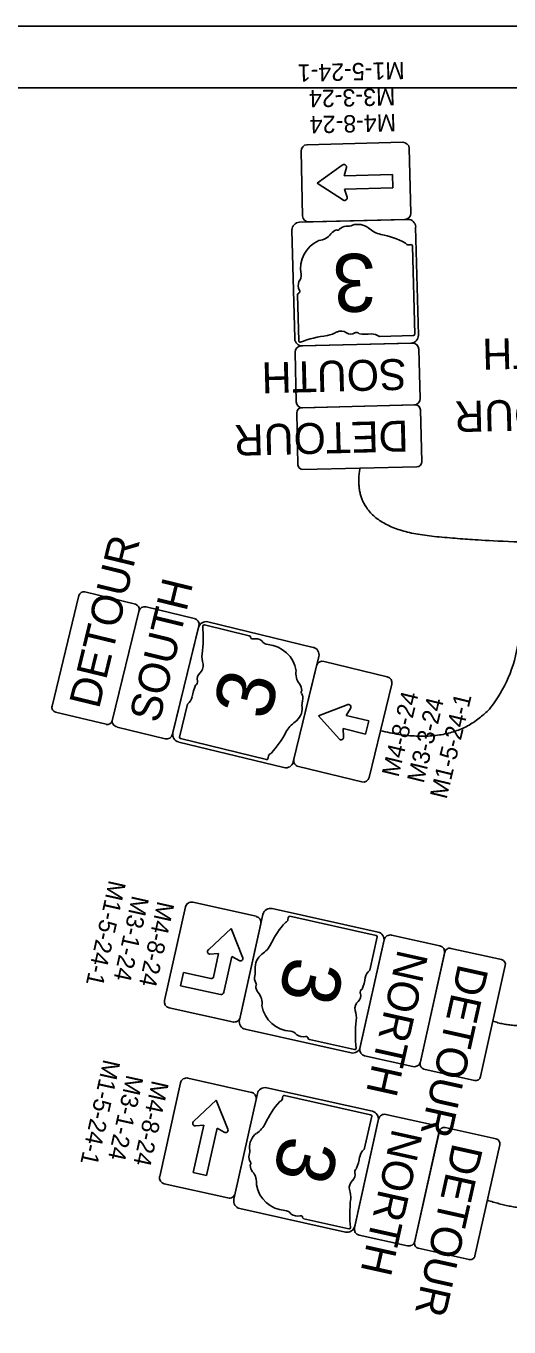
# Model space of a CAD drawing. Extents: x -15.3 to 34, y 0 to 22.
# Drawn here: x 16.96 to 20.86, y 11.48 to 22 of the extents above; entities that cross this region are included whole.
import ezdxf

# ---------------------------------------------------------------- set-up
doc = ezdxf.new("R2010")
doc.units = 0
for name, color, linetype in [('SC_Scratch1', 7, 'Continuous'), ('SH_Border', 7, 'Continuous'), ('SH_Cut_Line', 7, 'Continuous'), ('SH_Text', 7, 'Continuous'), ('SN_P_Signs', 7, 'Continuous')]:
    doc.layers.add(name, color=color, linetype=linetype)

msp = doc.modelspace()

# ---------------------------------------------------------------- linework, layer by layer
at = {"layer": 'SH_Border'}
msp.add_lwpolyline([(1.5, 21.5), (33.5, 21.5), (33.5, 0.5), (1.5, 0.5)], close=True, dxfattribs=at)
at = {"layer": 'SH_Cut_Line'}
msp.add_lwpolyline([(0, 0), (34, 0), (34, 22), (0, 22)], close=True, dxfattribs=at)
at = {"layer": 'SH_Text'}
for points in [[(19.655, 18.426), (19.572, 17.947), (20.883, 17.807), (23.028, 17.829), (24.003, 17.194), (24.244, 16.85)], [(19.821, 16.303), (20.813, 16.063), (21.093, 18.199), (23.713, 17.06), (23.897, 16.988), (23.961, 16.647)], [(20.729, 13.956), (21.193, 13.792), (22.671, 14.944), (23.628, 16.352), (23.835, 16.339)], [(20.684, 12.508), (21.281, 12.313), (22, 12.975), (23.853, 16.417), (24.116, 16.271)]]:
    msp.add_open_spline(points, degree=2, dxfattribs=at)
at = {"layer": 'SN_P_Signs'}
for p, q in [((19.227, 21.04), (20.002, 21.06)), ((19.192, 20.464), (19.179, 20.989)), ((20.053, 21.012), (20.067, 20.487)), ((19.511, 20.875), (19.31, 20.73)), ((19.528, 20.79), (19.546, 20.855)), ((19.31, 20.73), (19.521, 20.593)), ((19.918, 20.8), (19.528, 20.79)), ((19.921, 20.691), (19.918, 20.8)), ((19.531, 20.681), (19.921, 20.691)), ((19.552, 20.617), (19.531, 20.681)), ((20.018, 20.436), (19.244, 20.416)), ((20.097, 19.509), (20.079, 20.221)), ((19.151, 19.827), (19.161, 19.455)), ((19.151, 19.827), (19.151, 19.827)), ((19.814, 19.49), (20.088, 19.497)), ((19.141, 18.962), (19.131, 19.362)), ((19.18, 19.414), (20.079, 19.437)), ((20.131, 19.388), (20.141, 18.988)), ((20.092, 18.937), (19.193, 18.914)), ((17.656, 16.394), (17.868, 17.268)), ((17.929, 17.305), (18.317, 17.211)), ((18.354, 17.15), (18.142, 16.276)), ((18.761, 17.07), (18.4, 17.158)), ((18.761, 17.07), (18.761, 17.07)), ((19.122, 16.074), (19.305, 16.827)), ((19.365, 16.864), (19.875, 16.74)), ((19.912, 16.679), (19.729, 15.926)), ((18.262, 16.518), (18.197, 16.252)), ((19.32, 16.425), (19.551, 16.512)), ((19.487, 16.238), (19.32, 16.425)), ((19.58, 16.484), (19.545, 16.426)), ((19.545, 16.426), (19.727, 16.382)), ((18.081, 16.239), (17.693, 16.333)), ((19.701, 16.275), (19.519, 16.32)), ((19.519, 16.32), (19.523, 16.253)), ((19.727, 16.382), (19.701, 16.275)), ((18.207, 16.24), (18.899, 16.072)), ((19.669, 15.889), (19.159, 16.013)), ((18.077, 14.123), (18.245, 14.879)), ((18.305, 14.917), (18.817, 14.803)), ((18.855, 14.743), (18.687, 13.987)), ((19.785, 14.648), (19.09, 14.803)), ((18.614, 14.704), (18.434, 14.535)), ((18.706, 14.474), (18.614, 14.704)), ((19.735, 14.368), (19.795, 14.636)), ((19.91, 14.651), (20.301, 14.564)), ((19.655, 13.735), (19.851, 14.613)), ((18.44, 14.497), (18.513, 14.502)), ((18.513, 14.502), (18.471, 14.312)), ((18.555, 14.189), (18.62, 14.478)), ((18.62, 14.478), (18.684, 14.443)), ((20.339, 14.504), (20.143, 13.626)), ((18.231, 14.349), (18.207, 14.242)), ((18.231, 14.349), (18.207, 14.242)), ((18.452, 14.3), (18.231, 14.349)), ((18.207, 14.242), (18.528, 14.171)), ((18.555, 14.189), (18.555, 14.189)), ((18.627, 13.949), (18.115, 14.063)), ((19.247, 13.807), (19.61, 13.726)), ((19.247, 13.807), (19.247, 13.807)), ((20.083, 13.588), (19.693, 13.675)), ((18.778, 13.38), (18.266, 13.495)), ((18.206, 13.457), (18.038, 12.7)), ((18.314, 13.147), (18.495, 13.316)), ((18.495, 13.316), (18.589, 13.083)), ((18.648, 12.564), (18.816, 13.321)), ((19.74, 13.199), (19.045, 13.354)), ((19.61, 12.286), (19.806, 13.164)), ((19.69, 12.919), (19.75, 13.187)), ((19.865, 13.202), (20.256, 13.115)), ((18.309, 12.733), (18.394, 13.114)), ((18.394, 13.114), (18.327, 13.108)), ((18.501, 13.09), (18.416, 12.709)), ((18.559, 13.057), (18.501, 13.09)), ((20.294, 13.056), (20.098, 12.177)), ((18.416, 12.709), (18.309, 12.733)), ((18.075, 12.641), (18.588, 12.526)), ((18.648, 12.564), (18.648, 12.564)), ((19.202, 12.358), (19.565, 12.277)), ((19.202, 12.358), (19.202, 12.358)), ((20.038, 12.139), (19.648, 12.226))]:
    msp.add_line(p, q, dxfattribs=at)
for points in [[(20.041, 20.436), (19.166, 20.414)], [(19.106, 20.35), (19.128, 19.475)], [(20.128, 19.501), (20.105, 20.375)], [(19.192, 19.414), (20.067, 19.436)], [(20.102, 18.937), (19.183, 18.914)], [(19.144, 18.873), (19.154, 18.453)], [(20.154, 18.478), (20.143, 18.898)], [(19.195, 18.414), (20.115, 18.437)], [(17.385, 17.396), (17.168, 16.502)], [(17.841, 17.326), (17.433, 17.425)], [(17.654, 16.384), (17.871, 17.278)], [(19.277, 16.977), (18.427, 17.184)], [(18.351, 17.138), (18.145, 16.288)], [(19.116, 16.052), (19.323, 16.902)], [(17.197, 16.454), (17.605, 16.355)], [(18.191, 16.212), (19.041, 16.006)], [(19.801, 14.676), (18.947, 14.866)], [(18.872, 14.818), (18.682, 13.964)], [(19.658, 13.747), (19.848, 14.601)], [(20.341, 14.514), (20.141, 13.616)], [(20.799, 14.453), (20.389, 14.544)], [(20.629, 13.507), (20.829, 14.405)], [(18.729, 13.89), (19.583, 13.699)], [(20.171, 13.568), (20.581, 13.477)], [(18.827, 13.37), (18.637, 12.516)], [(19.756, 13.227), (18.902, 13.417)], [(19.613, 12.298), (19.803, 13.152)], [(20.296, 13.065), (20.096, 12.167)], [(20.754, 13.004), (20.344, 13.096)], [(20.584, 12.059), (20.784, 12.957)], [(18.684, 12.441), (19.538, 12.251)], [(20.126, 12.12), (20.536, 12.028)]]:
    msp.add_lwpolyline(points, dxfattribs=at)
for centre, radius, start, end in [((19.229, 20.99), 0.05, 91.4753, 181.4753), ((20.003, 21.01), 0.05, 1.4753, 91.4753), ((19.526, 20.86), 0.0209, 344.2707, 136.4849), ((19.532, 20.611), 0.0209, 236.8865, 18.6799), ((19.168, 20.351), 0.0625, 91.4753, 181.4753), ((19.242, 20.466), 0.05, 181.4753, 271.4753), ((20.017, 20.486), 0.05, 271.4753, 1.4753), ((20.043, 20.374), 0.0625, 1.4753, 91.4753), ((19.31, 20.401), 0.136, 275.8784, 324.052), ((19.486, 20.274), 0.0803, 104.3485, 144.7524), ((19.474, 20.372), 0.0214, 247.227, 314.1237), ((19.544, 20.305), 0.0759, 90.2523, 137.0246), ((19.55, 20.498), 0.117, 267.1704, 292.6852), ((19.638, 20.254), 0.143, 52.1757, 107.7671), ((19.874, 20.535), 0.225, 228.6595, 257.3113), ((19.684, 19.612), 0.718, 61.8882, 78.6738), ((19.424, 20.038), 0.249, 113.7842, 190.4611), ((20.048, 20.261), 0.0302, 211.2237, 274.747), ((20.068, 20.149), 0.0836, 88.8143, 102.0792), ((20.068, 20.222), 0.011, 353.4337, 79.7819), ((19.11, 19.982), 0.0705, 318.2818, 8.4049), ((19.254, 19.904), 0.097, 161.5083, 205.1249), ((19.162, 19.829), 0.0112, 111.0791, 189.2094), ((19.153, 19.855), 0.0162, 289.4193, 31.8123), ((19.191, 19.476), 0.0625, 181.4753, 271.4753), ((19.519, 18.512), 0.994, 97.3198, 110.3818), ((19.362, 19.696), 0.2, 278.8215, 302.2442), ((19.502, 19.458), 0.076, 55.3315, 116.3035), ((19.581, 19.573), 0.0632, 235.942, 300.6164), ((19.627, 19.492), 0.0304, 41.2674, 118.5777), ((19.703, 19.887), 0.378, 261.962, 276.4636), ((19.75, 19.406), 0.105, 53.0948, 92.5872), ((20.065, 19.499), 0.0625, 271.4753, 1.4753), ((20.086, 19.508), 0.0109, 279.6054, 9.6054), ((19.181, 19.364), 0.05, 91.4753, 181.4753), ((19.171, 19.454), 0.0104, 173.3374, 279.2133), ((20.081, 19.387), 0.05, 1.4753, 91.4753), ((19.191, 18.964), 0.05, 181.4753, 271.4753), ((20.091, 18.987), 0.05, 271.4753, 1.4753), ((20.103, 18.897), 0.04, 1.4753, 91.4753), ((19.184, 18.874), 0.04, 91.4753, 181.4753), ((19.194, 18.454), 0.04, 181.4753, 271.4753), ((20.114, 18.477), 0.04, 271.4753, 1.4753), ((17.424, 17.387), 0.04, 76.3401, 166.3401), ((17.832, 17.287), 0.04, 346.3401, 76.3401), ((17.917, 17.256), 0.05, 76.3401, 166.3401), ((18.306, 17.162), 0.05, 346.3401, 76.3401), ((18.412, 17.123), 0.0625, 76.3401, 166.3401), ((17.395, 17.058), 0.994, 352.1846, 5.2466), ((18.396, 17.148), 0.0104, 68.2022, 174.0781), ((18.76, 17.059), 0.0112, 5.9439, 84.0742), ((18.787, 17.061), 0.0162, 184.2841, 286.6771), ((18.809, 16.95), 0.097, 56.3731, 99.9897), ((18.921, 17.069), 0.0705, 213.1466, 263.2697), ((18.893, 16.751), 0.249, 8.649, 85.3259), ((19.262, 16.917), 0.0625, 346.3401, 76.3401), ((18.313, 16.827), 0.076, 310.1963, 11.1683), ((18.579, 16.901), 0.2, 173.6863, 197.109), ((19.353, 16.815), 0.05, 76.3401, 166.3401), ((18.404, 16.722), 0.0632, 130.8068, 195.4812), ((19.273, 16.767), 0.136, 170.7432, 218.9169), ((19.864, 16.691), 0.05, 346.3401, 76.3401), ((18.674, 16.522), 0.378, 156.8268, 171.3284), ((18.313, 16.698), 0.0304, 296.1322, 13.4425), ((19.105, 16.63), 0.0803, 359.2133, 39.6172), ((19.202, 16.616), 0.0214, 142.0918, 208.9885), ((18.197, 16.601), 0.105, 307.9596, 347.452), ((19.119, 16.565), 0.0759, 345.1171, 31.8894), ((19.304, 16.51), 0.117, 162.0352, 187.5501), ((19.562, 16.494), 0.0209, 329.1355, 121.3497), ((17.207, 16.493), 0.04, 166.3401, 256.3401), ((19.046, 16.488), 0.143, 307.0405, 2.6319), ((17.615, 16.393), 0.04, 256.3401, 346.3401), ((17.704, 16.382), 0.05, 166.3401, 256.3401), ((19.256, 16.187), 0.225, 123.5243, 152.1761), ((18.093, 16.287), 0.05, 256.3401, 346.3401), ((18.205, 16.273), 0.0625, 166.3401, 256.3401), ((18.208, 16.251), 0.0109, 174.4702, 264.4702), ((18.414, 16.612), 0.718, 316.753, 333.5386), ((19.503, 16.251), 0.0209, 221.7513, 3.5447), ((18.832, 16.101), 0.0836, 343.6791, 356.944), ((18.945, 16.091), 0.0302, 106.0885, 169.6119), ((18.903, 16.082), 0.011, 248.2985, 334.6467), ((19.056, 16.066), 0.0625, 256.3401, 346.3401), ((19.17, 16.062), 0.05, 166.3401, 256.3401), ((19.681, 15.938), 0.05, 256.3401, 346.3401), ((18.294, 14.868), 0.05, 77.4392, 167.4392), ((18.933, 14.805), 0.0625, 77.4392, 167.4392), ((18.806, 14.754), 0.05, 347.4392, 77.4392), ((19.585, 14.272), 0.718, 137.8521, 154.6377), ((19.044, 14.783), 0.0302, 287.1876, 350.7109), ((19.157, 14.775), 0.0836, 164.7782, 178.043), ((19.086, 14.792), 0.011, 69.3976, 155.7458), ((19.784, 14.637), 0.0109, 355.5693, 85.5693), ((19.787, 14.615), 0.0625, 347.4392, 77.4392), ((19.9, 14.602), 0.05, 77.4392, 167.4392), ((18.445, 14.518), 0.0209, 122.4393, 257.4408), ((18.735, 14.681), 0.225, 304.6233, 333.2752), ((20.29, 14.515), 0.05, 347.4392, 77.4392), ((20.38, 14.505), 0.04, 77.4392, 167.4392), ((18.689, 14.463), 0.0209, 257.4408, 32.439), ((18.951, 14.384), 0.143, 128.1396, 183.731), ((20.79, 14.414), 0.04, 347.4392, 77.4392), ((18.456, 14.315), 0.0156, 257.4392, 347.4392), ((18.879, 14.305), 0.0759, 166.2162, 212.9885), ((18.693, 14.357), 0.117, 343.1343, 8.6491), ((19.323, 14.357), 0.378, 337.9259, 352.4275), ((19.801, 14.286), 0.105, 129.0587, 168.5511), ((18.797, 14.253), 0.0214, 323.1909, 30.0876), ((18.894, 14.24), 0.0803, 180.3124, 220.7163), ((19.687, 14.188), 0.0304, 117.2312, 194.5416), ((18.125, 14.112), 0.05, 167.4392, 257.4392), ((18.533, 14.194), 0.0234, 257.4392, 347.4392), ((18.729, 14.1), 0.136, 351.8423, 40.0159), ((19.69, 14.058), 0.076, 131.2954, 192.2674), ((19.598, 14.162), 0.0632, 311.9059, 16.5803), ((19.109, 14.123), 0.249, 189.7481, 266.425), ((19.426, 13.98), 0.2, 354.7854, 18.208), ((18.638, 13.998), 0.05, 257.4392, 347.4392), ((18.743, 13.951), 0.0625, 167.4392, 257.4392), ((20.612, 13.845), 0.994, 173.2837, 186.3456), ((19.086, 13.805), 0.0705, 34.2457, 84.3688), ((19.197, 13.926), 0.097, 237.4721, 281.0888), ((19.22, 13.815), 0.0162, 5.3832, 107.7762), ((19.248, 13.818), 0.0112, 187.043, 265.1733), ((19.597, 13.76), 0.0625, 257.4392, 347.4392), ((19.614, 13.736), 0.0104, 249.3013, 355.1772), ((19.704, 13.724), 0.05, 167.4392, 257.4392), ((20.094, 13.637), 0.05, 257.4392, 347.4392), ((20.18, 13.607), 0.04, 167.4392, 257.4392), ((18.255, 13.446), 0.05, 77.4392, 167.4392), ((20.59, 13.516), 0.04, 257.4392, 347.4392), ((18.767, 13.332), 0.05, 347.4392, 77.4392), ((18.888, 13.356), 0.0625, 77.4392, 167.4392), ((19.54, 12.823), 0.718, 137.8521, 154.6377), ((18.999, 13.334), 0.0302, 287.1876, 350.7109), ((19.112, 13.326), 0.0836, 164.7782, 178.043), ((19.041, 13.344), 0.011, 69.3976, 155.7458), ((18.325, 13.129), 0.0209, 122.4296, 274.6438), ((19.739, 13.188), 0.0109, 355.5693, 85.5693), ((19.742, 13.166), 0.0625, 347.4392, 77.4392), ((19.855, 13.153), 0.05, 77.4392, 167.4392), ((18.569, 13.075), 0.0209, 240.2346, 22.028), ((18.906, 12.935), 0.143, 128.1396, 183.731), ((18.691, 13.232), 0.225, 304.6233, 333.2752), ((20.245, 13.067), 0.05, 347.4392, 77.4392), ((20.335, 13.057), 0.04, 77.4392, 167.4392), ((20.745, 12.965), 0.04, 347.4392, 77.4392), ((18.834, 12.856), 0.0759, 166.2162, 212.9885), ((18.648, 12.908), 0.117, 343.1343, 8.6491), ((19.278, 12.908), 0.378, 337.9259, 352.4275), ((19.756, 12.838), 0.105, 129.0587, 168.5511), ((18.752, 12.804), 0.0214, 323.1909, 30.0876), ((18.849, 12.791), 0.0803, 180.3124, 220.7163), ((18.684, 12.651), 0.136, 351.8423, 40.0159), ((19.553, 12.714), 0.0632, 311.9059, 16.5803), ((19.643, 12.739), 0.0304, 117.2312, 194.5416), ((18.086, 12.689), 0.05, 167.4392, 257.4392), ((19.064, 12.674), 0.249, 189.7481, 266.425), ((19.645, 12.609), 0.076, 131.2954, 192.2674), ((18.599, 12.575), 0.05, 257.4392, 347.4392), ((18.698, 12.502), 0.0625, 167.4392, 257.4392), ((19.381, 12.531), 0.2, 354.7854, 18.208), ((19.041, 12.356), 0.0705, 34.2457, 84.3688), ((20.567, 12.396), 0.994, 173.2837, 186.3456), ((19.152, 12.477), 0.097, 237.4721, 281.0888), ((19.176, 12.367), 0.0162, 5.3832, 107.7762), ((19.203, 12.37), 0.0112, 187.043, 265.1733), ((19.552, 12.312), 0.0625, 257.4392, 347.4392), ((19.569, 12.287), 0.0104, 249.3013, 355.1772), ((19.659, 12.275), 0.05, 167.4392, 257.4392), ((20.049, 12.188), 0.05, 257.4392, 347.4392), ((20.135, 12.159), 0.04, 167.4392, 257.4392), ((20.545, 12.067), 0.04, 257.4392, 347.4392)]:
    msp.add_arc(centre, radius, start, end, dxfattribs=at)

# ---------------------------------------------------------------- texts
at = {"layer": 'SC_Scratch1'}
for s, rotation, p in [('M1-5-24-1', 181.4753, (20.014, 21.711)), ('M3-3-24', 181.4753, (19.939, 21.499)), ('M4-8-24', 181.4753, (19.945, 21.289)), ('M4-8-24', 76.3401, (19.965, 15.922)), ('M3-3-24', 76.3401, (20.169, 15.873)), ('M1-5-24-1', 76.3401, (20.354, 15.745)), ('M1-5-24-1', 257.4392, (17.629, 15.101)), ('M3-1-24', 257.4392, (17.816, 14.977)), ('M4-8-24', 257.4392, (18.021, 14.932)), ('M1-5-24-1', 257.4392, (17.584, 13.653)), ('M3-1-24', 257.4392, (17.771, 13.528)), ('M4-8-24', 257.4392, (17.976, 13.483))]:
    msp.add_text(s, height=0.14, rotation=rotation, dxfattribs=at).set_placement(p)
at = {"layer": 'SN_P_Signs'}
for s, height, rotation, p in [('3', 0.469, 181.4753, (19.778, 20.163)), ('SOUTH', 0.25, 181.4753, (21.81, 19.501)), ('SOUTH', 0.25, 181.4753, (20.028, 19.31)), ('DETOUR', 0.25, 181.4753, (21.825, 19.002)), ('DETOUR', 0.25, 181.4753, (20.044, 18.811)), ('DETOUR', 0.25, 76.3401, (17.547, 16.473)), ('SOUTH', 0.25, 76.3401, (18.033, 16.358)), ('3', 0.469, 76.3401, (18.921, 16.377)), ('NORTH', 0.25, 257.4392, (19.963, 14.544)), ('3', 0.469, 257.4392, (19.073, 14.497)), ('DETOUR', 0.25, 257.4392, (20.45, 14.427)), ('NORTH', 0.25, 257.4392, (19.918, 13.095)), ('3', 0.469, 257.4392, (19.028, 13.048)), ('DETOUR', 0.25, 257.4392, (20.405, 12.978))]:
    msp.add_text(s, height=height, rotation=rotation, dxfattribs=at).set_placement(p)

doc.saveas('drawing.dxf')
